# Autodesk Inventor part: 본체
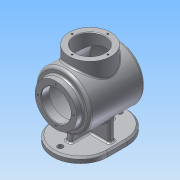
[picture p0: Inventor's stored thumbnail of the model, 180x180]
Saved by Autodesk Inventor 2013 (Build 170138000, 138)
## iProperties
Created: 2016-04
Part Number: 본체
Material: 알루미늄 6061
Document SubType Name: Modeling
Designer: Administrator
Density: 2.71 g/cm^3
Mass: 909.636 g
Surface Area: 1226.76 cm^2
Volume: 335.659 cm^3
Author: Administrator
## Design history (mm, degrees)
sketch "스케치1"
  geometry: L1 (-17.5, 50)-(17.5, 50); L2 (17.5, -50)-(-17.5, -50); A1 r 50 centre (-17.5, 0) between (-17.5, 50) and (-17.5, -50); A2 r 50 centre (17.5, 0) between (17.5, -50) and (17.5, 50); 3 further points
  constraints: 5 point on circle, 4 end point, 4 tangent, 3 horizontal alignment, 2 centre point, 1 midpoint, 1 parallel, 1 vertical alignment
  dimensions: "d0" = 100 diameter of A1; "d2" = 135 dimension on A2 A1; "d3" = 67.49999 distance of point (-67.5, 0) point (0, 0)
extrude "돌출1" new body sketch "스케치1" distance "d4" = 10; taper "d5" = 0 deg
sketch "스케치2"
  geometry: L1 (67.5, 10)-(17.5, 10) reference; L2 (17.5, 10)-(-17.5, 10) reference; L3 (-17.5, 10)-(-67.5, 10) reference; L4 (-40, 10)-(-27.833, 79); L5 (-27.833, 79)-(27.833, 79); L6 (27.833, 79)-(40, 10); 1 further point
  constraints: 6 end point, 2 point on line, 1 parallel
  dimensions: "d6" = 40 horizontal distance of L6.end point (0, 0); "d7" = 40 horizontal distance of point (0, 0) L4.start; "d8" = 100 deg angle of L3 L4; "d9" = 100 deg angle of L1 L6; "d10" = 69 distance between parallel lines of L2 L5
extrude "돌출2" join sketch "스케치2" stored distance "d11" = 10; taper "d12" = 0 deg
sketch "스케치3"
  geometry: L1 (50, 10)-(-50, 10) reference; L2 (-40, 10)-(-40, 79); L3 (-40, 79)-(40, 79); L4 (40, 79)-(40, 10); 1 further point
  constraints: 6 end point, 2 point on line, 1 parallel
  dimensions: "d13" = 40 horizontal distance of point (0, 0) L4.end; "d14" = 40 horizontal distance of point (0, 0) L2.start; "d15" = 90 deg angle of L1 L2; "d16" = 90 deg angle of L1 L4; "d17" = 69 distance between parallel lines of L1 L3
extrude "돌출3" join sketch "스케치3" stored distance "d18" = 10; taper "d19" = 0 deg
sketch "스케치4"
  geometry: L1 (5, 79)-(-5, 79) reference; L2 (-62, 79)-(60, 79); L3 (-62, 79)-(-62, 117); L4 (-62, 117)-(-50, 117); L5 (-50, 117)-(-50, 129); L6 (-50, 129)-(49.087, 129); A1 r 120 centre (-60, 79) between (60, 79) and (49.087, 129); 2 further points
  constraints: 10 end point, 2 parallel, 2 perpendicular, 2 point on circle, 1 centre point, 1 horizontal alignment, 1 midpoint, 1 point on line
  dimensions: "d20" = 122 distance of L2.start L2.end; "d22" = 12 distance of L3.end L4.end; "d24" = 50 horizontal distance of L4.end point (0, 79); "d25" = 110 horizontal distance of L2.end L5.end; "d26" = 120 radius of A1; "d27" = 100 diameter of L6 L2; "d28" = 76 diameter of L4 L2
revolve "회전1" sketch "스케치4" stored, may be unused: angle "d29" = 90 deg
node "작업 평면1"
sketch "스케치5"
  geometry: C1 r 38 at (0, 0); 1 further point
  constraints: 1 centre point, 1 coincident
  dimensions: "d31" = 76 diameter of C1
extrude "돌출4" join sketch "스케치5" distance "d33" = 50; taper "d34" = 0 deg
sketch "스케치6"
  geometry: C1 r 5 at (-54, 0); C2 r 5 at (54, 0); 1 further point
  constraints: 2 centre point, 2 horizontal alignment
  dimensions: "d35" = 10 diameter of C1; "d37" = 10 diameter of C2; "d38" = 54 distance of point (0, 0) C1.centre; "d39" = 54 distance of C2.centre point (0, 0)
extrude "돌출5" cut sketch "스케치6" distance "d40" = 50; taper "d41" = 0 deg
node "작업 평면3"
sketch "스케치7"
  geometry: L1 (-50, 129)-(49.087, 129) reference; L2 (-50, 29)-(49.087, 29) reference; L3 (-50, 29)-(-50, 129) reference; L4 (47.145, 126)-(-47, 126); L5 (-47, 126)-(-47, 79); L6 (-47, 79)-(57, 79); A1 r 120 centre (-60, 79) between (49.087, 29) and (49.087, 129) reference; A2 r 117 centre (-60, 79) between (57, 79) and (47.145, 126); 1 further point
  constraints: 6 end point, 2 parallel, 2 point on circle, 1 centre point
  dimensions: "d42" = 3 radial gap between concentric circles of A1 A2; "d43" = 3 distance between parallel lines of L4 L1; "d44" = 3 distance between parallel lines of L5 L3; "d105" = 94 diameter of L4 L6
hole "구멍1" diameter "d49" = 54; stored, may be unused: countersink angle "d53" = 90 deg, drill point angle "d55" = 118 deg; dims "d47" = 10, "d48" = 10, "d50" = 6, "d51" = 4, "d52" = 2, "d54" = 40
hole "구멍2" diameter "d58" = 54; stored, may be unused: countersink angle "d62" = 90 deg, drill point angle "d64" = 118 deg; dims "d56" = 10, "d57" = 10, "d59" = 6, "d60" = 4, "d61" = 2, "d63" = 40
sketch "스케치11"
  geometry: L1 (-29.035, 83.203)-(29.035, 83.203); L2 (29.035, 83.203)-(29.035, 74.797); L3 (29.035, 74.797)-(-29.035, 74.797); L4 (-29.035, 74.797)-(-29.035, 83.203); C1 r 50 at (0, 79) reference; 4 further points
  constraints: 2 midpoint, 1 coincident, 1 horizontal, 1 horizontal alignment, 1 vertical alignment, 2 other
  dimensions: "d90" = 58.07055 distance between parallel lines of L2 L4; "d91" = 8.4057 distance between parallel lines of L3 L1
feature "엠보싱2" dims "d0" = 100, "d2" = 135, "d3" = 67.49999, "d94" = 0.5, "d95" = 0
revolve "회전2" stored, may be unused: angle "d46" = 90 deg
chamfer "모따기1" distance "d66" = 3; stored, may be unused: second distance "d67" = 2, angle "d68" = 45 deg
sketch "스케치8"
  geometry: C1 r 38 at (0, 0) reference; A1 r 32.5 centre (0, 0) between (0, 32.5) and (-32.5, 0); 3 further points
  constraints: 4 point on circle, 2 horizontal alignment, 2 vertical alignment, 1 centre point, 1 coincident
  dimensions: "d69" = 65 diameter of A1
hole "구멍3" sketch "스케치8" at (0, 32.5), (-32.5, 0), (0, -32.5), (32.5, 0) diameter "d71" = 3.242; stored, may be unused: countersink angle "d75" = 90 deg, drill point angle "d77" = 118 deg; dims "d72" = 8, "d73" = 4, "d74" = 2, "d76" = 10
sketch "스케치9"
  geometry: A1 r 32.5 centre (0, 0) between (0, 32.5) and (-32.5, 0); 3 further points
  constraints: 4 point on circle, 2 horizontal alignment, 2 vertical alignment, 1 centre point, 1 coincident
  dimensions: "d78" = 65 diameter of A1
hole "구멍4" sketch "스케치9" at (0, 32.5), (-32.5, 0), (0, -32.5), (32.5, 0) diameter "d80" = 3.242; stored, may be unused: countersink angle "d84" = 90 deg, drill point angle "d86" = 118 deg; dims "d81" = 8, "d82" = 4, "d83" = 2, "d85" = 10
fillet "모깎기2" dims "d96" = 2
fillet "모깎기3" dims "d97" = 5
fillet "모깎기4" dims "d98" = 5
fillet "모깎기5" dims "d99" = 3
fillet "모깎기6" dims "d100" = 3
fillet "모깎기7" dims "d101" = 3
chamfer "모따기2" distance "d102" = 1; stored, may be unused: second distance "d103" = 2, angle "d104" = 45 deg
node "솔리드1"
other parameters: "d30" = 144, "d89" = 0
